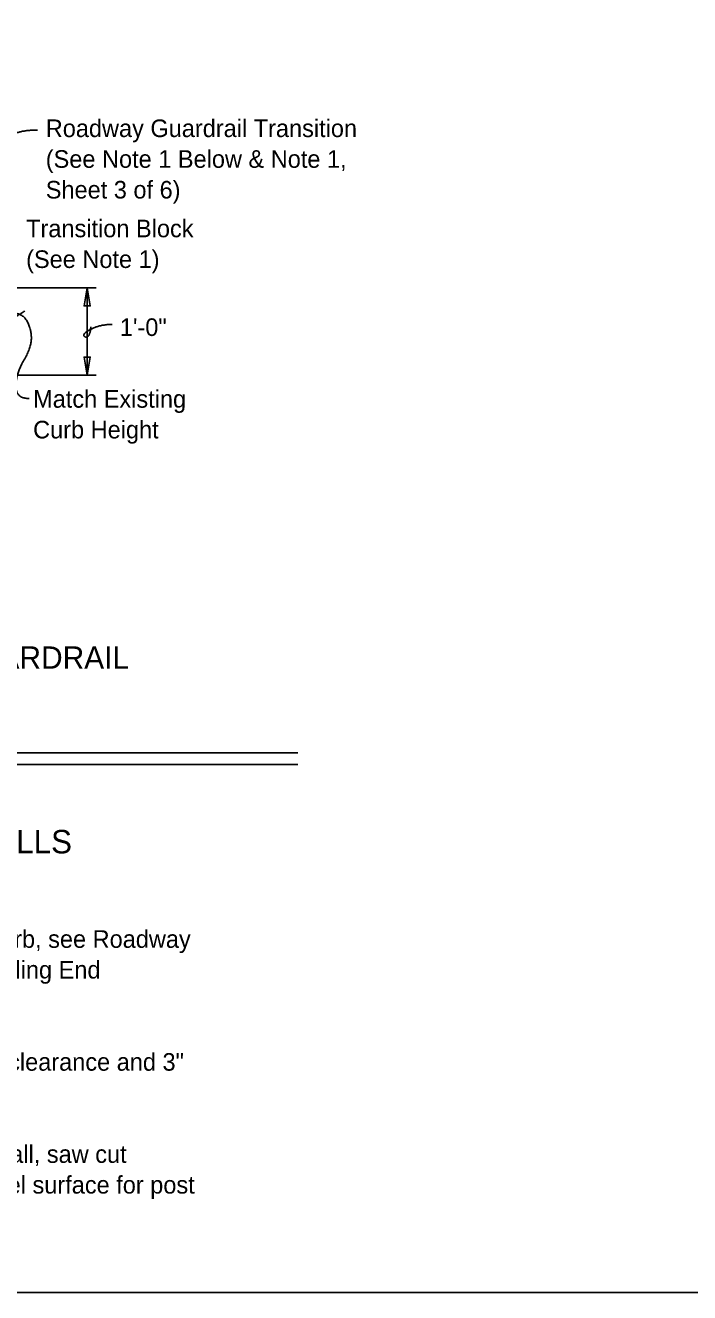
# Model space of a CAD drawing. Extents: x 1.5 to 68.7, y 0 to 31.
# Drawn here: x 12.85 to 20.46, y 1.78 to 16.3 of the extents above; entities that cross this region are included whole.
import ezdxf

# ---------------------------------------------------------------- set-up
doc = ezdxf.new("R2010")
doc.units = 0
for name, color, linetype in [('ActivePts-ConstElements', 7, 'Continuous'), ('Dimension', 7, 'Continuous'), ('TextStructures', 7, 'Continuous')]:
    doc.layers.add(name, color=color, linetype=linetype)

# ---------------------------------------------------------------- blocks, each defined once
blk = doc.blocks.new('Terminator-Arrow')
at = {"layer": 'Dimension'}
blk.add_lwpolyline([(0, 0), (-0.00041, 0.000069), (-0.00041, -0.000069)], close=True, dxfattribs=at)

msp = doc.modelspace()

# ---------------------------------------------------------------- linework, layer by layer
at = {"layer": 'ActivePts-ConstElements'}
msp.add_lwpolyline([(1.467, 28.183), (42.533, 28.183), (42.533, 1.783), (1.467, 1.783)], close=True, dxfattribs=at)
at = {"layer": 'Dimension'}
for p, q in [((10.687, 13.296), (13.662, 13.296)), ((13.562, 13.296), (13.562, 12.296)), ((10.687, 12.296), (13.662, 12.296)), ((11.614, 7.968), (15.974, 7.968)), ((11.614, 7.835), (15.974, 7.835))]:
    msp.add_line(p, q, dxfattribs=at)
for points in [[(12.992, 15.103), (12.706, 15.112), (12.429, 14.783), (12.063, 14.685), (11.893, 14.586)], [(12.894, 12.029), (12.743, 12.029), (12.743, 12.31), (12.921, 12.612), (12.921, 12.831), (12.818, 13.003), (12.647, 13.003), (12.571, 12.921), (12.674, 12.921), (12.846, 13.03)], [(13.603, 12.849), (13.587, 12.708), (13.486, 12.76), (13.703, 12.877), (13.845, 12.877)]]:
    msp.add_open_spline(points, degree=2, dxfattribs=at)

# ---------------------------------------------------------------- block references
at = {"layer": 'Dimension', "xscale": 506.349, "yscale": -512.1577380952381}
for p, rotation in [((13.561, 13.296), 90), ((13.561, 12.296), -90)]:
    msp.add_blockref('Terminator-Arrow', p, dxfattribs=dict(at, rotation=rotation))

# ---------------------------------------------------------------- texts
at = {"layer": 'Dimension'}
for s, height, p in [('Roadway Guardrail Transition', 0.2016, (13.086, 15.024)), ('(See Note 1 Below & Note 1,', 0.2016, (13.086, 14.672)), ('Sheet 3 of 6)', 0.2016, (13.086, 14.32)), ('Transition Block', 0.2016, (12.861, 13.876)), ('(See Note 1)', 0.2016, (12.861, 13.524)), ('Match Existing ', 0.2016, (12.941, 11.923)), ('Curb Height', 0.2016, (12.941, 11.571)), ('PARTIAL ELEVATION OF INSIDE FACE OF GUARDRAIL', 0.256, (5.119, 8.932)), ('PERPENDICULAR OR ANGLED WING WALLS', 0.2688, (5.717, 6.816)), ('1. Provide Transition Block (as shown) or Curb if existing Approach Slab does not have a curb, see Roadway ', 0.2016, (1.755, 5.734)), ('   Plans.  Shape and height of Transition Block or Curb shall match existing bridge curb.  Railing End ', 0.2016, (1.755, 5.382)), ('2. Field bend Dowel Bars 4L within Transition Block as required to maintain 2" top and side clearance and 3" ', 0.2016, (1.755, 4.326)), ('3. If a Special Steel Guardrail Post is required for attachment to the top of a sloping Wing Wall, saw cut ', 0.2016, (1.755, 3.27)), ('   and remove a wedge shaped portion of the sloping Wing Wall as required to provide a level surface for post', 0.2016, (1.755, 2.918))]:
    msp.add_text(s, height=height, dxfattribs=at).set_placement(p)
at = {"layer": 'TextStructures'}
msp.add_text('1\'-0"', height=0.2016, dxfattribs=at).set_placement((13.935, 12.745))

doc.saveas('drawing.dxf')
